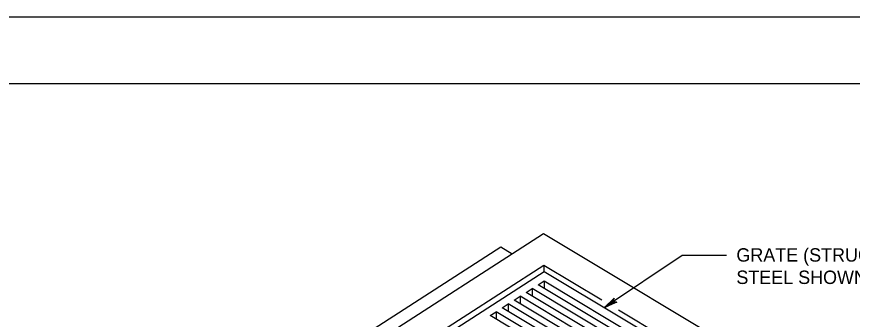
# Model space of a CAD drawing. Extents: x -6420 to 49575, y -4552 to 11624.
# Drawn here: x 5965 to 6578, y 11402 to 11624 of the extents above; entities that cross this region are included whole.
import ezdxf

# ---------------------------------------------------------------- set-up
doc = ezdxf.new("R2010")
doc.units = 0
doc.layers.add('1', color=7, linetype='Continuous')
doc.layers.add('PLT-BNDY', color=7, linetype='Continuous')

msp = doc.modelspace()

# ---------------------------------------------------------------- linework, layer by layer
at = {"layer": '1'}
for p, q in [((6027.11, 11265.77), (6320.36, 11454.97)), ((6320.36, 11454.97), (6328.85, 11449.87)), ((6352.08, 11441.43), (6352.08, 11436.8)), ((6347.87, 11427.1), (6352.27, 11429.94)), ((6449.01, 11366.41), (6347.87, 11427.1)), ((6352.27, 11429.94), (6453.42, 11369.24)), ((6352.27, 11429.94), (6352.27, 11424.46)), ((6339.09, 11421.43), (6343.49, 11424.27)), ((6440.23, 11360.74), (6339.09, 11421.43)), ((6444.62, 11363.58), (6343.49, 11424.27)), ((6343.49, 11424.27), (6343.49, 11418.8)), ((6330.31, 11415.76), (6334.7, 11418.6)), ((6431.44, 11355.08), (6330.31, 11415.76)), ((6435.84, 11357.91), (6334.7, 11418.6)), ((6334.7, 11418.6), (6334.7, 11413.13)), ((6321.51, 11410.09), (6325.91, 11412.93)), ((6422.66, 11349.41), (6321.51, 11410.09)), ((6427.05, 11352.24), (6325.91, 11412.93)), ((6325.91, 11412.93), (6325.91, 11407.46)), ((6312.73, 11404.43), (6317.12, 11407.25)), ((6413.87, 11343.74), (6312.73, 11404.43)), ((6418.26, 11346.57), (6317.12, 11407.25)), ((6317.12, 11407.25), (6317.12, 11401.78))]:
    msp.add_line(p, q, dxfattribs=at)
for points in [[(7323.07, 9724.29), (7323.07, 11574.68), (4744.33, 11574.68), (4744.33, 9724.29), (7323.07, 9724.29), (7323.07, 9810.77), (6666.9, 9810.77), (6666.9, 10022.97), (7323.07, 10022.97), (7323.07, 10117.99), (6666.9, 10117.99), (6666.9, 9724.29), (6925.44, 9724.29), (6925.44, 9810.77), (6925.44, 9724.29), (7178.06, 9724.29), (7178.06, 9810.77), (7178.06, 9770.36), (7323.07, 9770.36)], [(6265.08, 11212.65), (6107.6, 11307.14), (6351.7, 11464.62), (6509.18, 11370.13), (6265.08, 11212.65)], [(6486.02, 11448.58), (6453.61, 11448.58), (6396.44, 11410.23)], [(6264.71, 11235.83), (6144.85, 11307.75), (6352.08, 11441.43), (6394.51, 11415.97)], [(6264.63, 11240.47), (6152.31, 11307.86), (6352.15, 11436.8), (6464.48, 11369.4), (6264.63, 11240.47)], [(6396.44, 11410.23), (6403.54, 11417.2), (6403.37, 11416.77), (6403.2, 11416.35), (6403.23, 11415.97), (6403.25, 11415.59), (6403.38, 11415.28), (6403.52, 11414.98), (6403.75, 11414.74), (6403.98, 11414.5), (6404.32, 11414.33), (6404.67, 11414.17), (6405.13, 11414.16), (6405.58, 11414.15), (6396.44, 11410.23), (6405.13, 11414.16), (6404.67, 11414.17), (6396.44, 11410.23), (6404.32, 11414.33), (6403.98, 11414.5), (6396.44, 11410.23), (6403.75, 11414.74), (6403.52, 11414.98), (6396.44, 11410.23), (6403.38, 11415.28), (6403.25, 11415.59), (6396.44, 11410.23), (6403.23, 11415.97), (6403.2, 11416.35), (6396.44, 11410.23), (6403.37, 11416.77)], [(6406.77, 11408.62), (6471.93, 11369.52), (6264.71, 11235.83)]]:
    msp.add_lwpolyline(points, dxfattribs=at)
at = {"layer": 'PLT-BNDY'}
msp.add_lwpolyline([(4616.38, 11623.9), (7375.57, 11623.9), (7375.57, 9675.08), (4616.38, 9675.08)], close=True, dxfattribs=at)

# ---------------------------------------------------------------- texts
at = {"layer": '1'}
for s, p in [('GRATE (STRUCTURAL', (6493.35, 11444.02)), ('STEEL SHOWN)', (6493.35, 11427.61))]:
    msp.add_text(s, height=9.8425, dxfattribs=at).set_placement(p)

doc.saveas('drawing.dxf')
